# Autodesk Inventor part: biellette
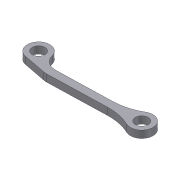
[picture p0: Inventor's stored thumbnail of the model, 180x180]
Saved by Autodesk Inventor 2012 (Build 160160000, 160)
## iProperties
Created: 2011-07
Part Number: biellette
Document SubType Name: Modeling
Designer: Laur
Density: 7.85 g/cm^3
Material: Acier allié
Mass: 1.60439 g
Surface Area: 4.18721 cm^2
Volume: 0.204381 cm^3
Author: Laur
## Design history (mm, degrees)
sketch "Esquisse1"
  geometry: L1 (21.191, -119.315)-(77.427, -119.427); L2 (77.427, -119.427)-(77.337, -164.658); L3 (77.337, -164.658)-(21.101, -164.546); L4 (21.101, -164.546)-(21.191, -119.315); L5 (25.447, -163.965)-(75.444, -163.428); L6 (42.012, -137.241)-(57.461, -136.823); L7 (41.744, -139.349)-(58.039, -138.908); L8 (34.517, -138.047)-(40.876, -139.278); C1 r 1.78 at (35.106, -135.004); C2 r 1.78 at (66.106, -137.504); A1 r 3.1 centre (35.106, -135.004) between (38.118, -134.268) and (34.517, -138.047); A2 r 3.1 centre (66.106, -137.504) between (64.793, -140.312) and (64.556, -134.819); A3 r 3.9 centre (41.906, -133.342) between (38.118, -134.268) and (42.012, -137.241); A4 r 4 centre (41.636, -135.35) between (40.876, -139.278) and (41.744, -139.349); A5 r 15 centre (58.445, -153.903) between (64.793, -140.312) and (58.039, -138.908); A6 r 15 centre (57.056, -121.829) between (57.461, -136.823) and (64.556, -134.819); 1 further point; 1 other entity
  constraints: 12 point on circle, 9 tangent, 8 centre point, 8 end point, 2 coincident, 2 point on line, 1 parallel, 3 other
  dimensions: "d32" = 50 distance of L5.start L5.end; "d82" = 3.56 diameter of C1; "d83" = 3.56 diameter of C2 (= d82); "d84" = 6.2 diameter of A1; "d85" = 6.2 diameter of A2 (= d84); "d86" = 2.1 distance between parallel lines of L7 L6; "d87" = 7.8 diameter of A3; "d88" = 6.8 horizontal distance of A3.centre C1.centre; "d89" = 167.5 deg angle of L7 L8; "d90" = 6.2 horizontal distance of point (41.306, -139.361) A1.centre; "d91" = 4 radius of A4; "d92" = 30 diameter of A5; "d96" = 30 diameter of A6 (= d92); "d110" = 31.1 distance of C2.centre C1.centre; "d111" = 2.5 vertical distance of A2.centre C1.centre
extrude "formes dont Ø3,56" new body sketch "Esquisse1" distance "d100" = 2; taper "d101" = 0 deg
sketch "Esquisse3"
  geometry: L1 (42.012, -137.241)-(57.461, -136.823) reference; L2 (40.876, -139.278)-(34.517, -138.047) reference; L3 (58.039, -138.908)-(41.744, -139.349) reference; C1 r 1.78 at (66.106, -137.504) reference; C2 r 1.78 at (35.106, -135.004) reference; A1 r 15 centre (57.056, -121.829) between (57.461, -136.823) and (64.556, -134.819) reference; A2 r 3.9 centre (41.906, -133.342) between (38.118, -134.268) and (42.012, -137.241) reference; A3 r 3.1 centre (35.106, -135.004) between (38.118, -134.268) and (34.517, -138.047) reference; A4 r 4 centre (41.636, -135.35) between (40.876, -139.278) and (41.744, -139.349) reference; A5 r 15 centre (58.445, -153.903) between (64.793, -140.312) and (58.039, -138.908) reference; A6 r 3.1 centre (66.106, -137.504) between (64.793, -140.312) and (64.556, -134.819) reference
node "Axe de construction1"
node "Solide1"
node "Corps solides"
node "Corps surfaciques"
node "Image2"
other parameters: "d114" = 60000, "sa_eq_min" = 13485.7, "sa_eq_max" = 1.28976e+07, "sa_pmax_min" = -386809, "sa_pmax_max" = 9999680, "sa_pmin_min" = -1.3015e+07, "sa_pmin_max" = 306964, "sa_d_min" = 0, "sa_d_max" = 0.12352, "sa_sf_min" = 19.3835
